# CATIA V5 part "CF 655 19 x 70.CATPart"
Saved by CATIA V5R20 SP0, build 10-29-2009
Part number: CF 655 19 x 70
Definition: NONE
Nomenclature: CF 655 19 x 70
Source: Unknown
Description: CF 655 19 x 70
Bounding box of the stored display mesh (mm): x -52 to 18, y -17 to 17, z -17 to 17
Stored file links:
  C:\Users\Utente\Desktop\IO LAVORO\3D X SITO CF\X SITO\CF 655\CF 655 19 x 70.CATPart
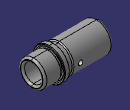
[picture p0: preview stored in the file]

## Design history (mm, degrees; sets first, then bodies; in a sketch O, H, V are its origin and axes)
Body1 "CF 655 19 x 70" (main body)
  Solid1: solid without history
